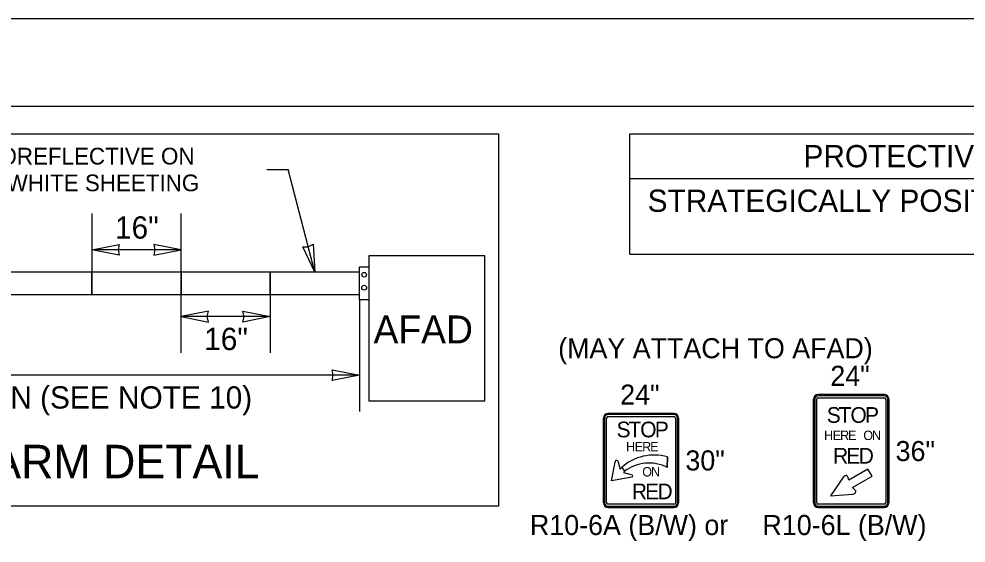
# Model space of a CAD drawing. Extents: x 99999.1 to 100095.7, y 99995 to 100010.7.
# Drawn here: x 100009.243 to 100012.641, y 100008.806 to 100010.687 of the extents above; entities that cross this region are included whole.
import ezdxf

# ---------------------------------------------------------------- set-up
doc = ezdxf.new("R2010")
doc.units = 0
for name, color, linetype in [('SH_GI_PlotLimits', 7, 'Continuous'), ('SH_GI_SheetBorder', 7, 'Continuous'), ('SH_TI_Tables', 7, 'Continuous'), ('TR_SN_ConstructionSigns', 7, 'Continuous'), ('TR_WZ_WorkZoneDetails', 7, 'Continuous')]:
    doc.layers.add(name, color=color, linetype=linetype)

msp = doc.modelspace()

# ---------------------------------------------------------------- linework, layer by layer
at = {"layer": 'SH_GI_PlotLimits'}
msp.add_lwpolyline([(99999.0625, 99999.6875), (100016.0625, 99999.6875), (100016.0625, 100010.6875), (99999.0625, 100010.6875)], close=True, dxfattribs=at)
at = {"layer": 'SH_GI_SheetBorder'}
msp.add_line((100000, 100010.375), (100015.75, 100010.375), dxfattribs=at)
at = {"layer": 'SH_TI_Tables'}
for p, q in [((100011.4347, 100009.843), (100011.4347, 100010.275)), ((100011.4347, 100010.275), (100015.65, 100010.275)), ((100011.4347, 100010.115), (100015.65, 100010.115)), ((100011.4347, 100009.843), (100015.65, 100009.843))]:
    msp.add_line(p, q, dxfattribs=at)
at = {"layer": 'TR_SN_ConstructionSigns'}
for p, q in [((100012.347, 100009.3391), (100012.1108, 100009.3391)), ((100012.1108, 100009.3391), (100012.347, 100009.3391)), ((100012.347, 100009.3391), (100012.1108, 100009.3391)), ((100012.347, 100009.3349), (100012.1108, 100009.3349)), ((100012.0939, 100009.3222), (100012.0939, 100008.951)), ((100012.0939, 100008.951), (100012.0939, 100009.3222)), ((100012.0939, 100009.3222), (100012.0939, 100008.951)), ((100012.0981, 100009.3222), (100012.0981, 100008.951)), ((100012.1052, 100008.951), (100012.1052, 100009.3222)), ((100012.1108, 100009.3279), (100012.347, 100009.3279)), ((100012.3527, 100009.3222), (100012.3527, 100008.951)), ((100012.3597, 100008.951), (100012.3597, 100009.3222)), ((100012.3639, 100008.951), (100012.3639, 100009.3222)), ((100012.3639, 100009.3222), (100012.3639, 100008.951)), ((100012.3639, 100008.951), (100012.3639, 100009.3222)), ((100011.5928, 100009.2716), (100011.3566, 100009.2716)), ((100011.3566, 100009.2716), (100011.5928, 100009.2716)), ((100011.5928, 100009.2716), (100011.3566, 100009.2716)), ((100011.3566, 100009.2716), (100011.5928, 100009.2716)), ((100011.5928, 100009.2674), (100011.3566, 100009.2674)), ((100011.3397, 100009.2547), (100011.3397, 100008.951)), ((100011.3397, 100008.951), (100011.3397, 100009.2547)), ((100011.3397, 100009.2547), (100011.3397, 100008.951)), ((100011.3397, 100008.951), (100011.3397, 100009.2547)), ((100011.3439, 100009.2547), (100011.3439, 100008.951)), ((100011.351, 100008.951), (100011.351, 100009.2547)), ((100011.3566, 100009.2604), (100011.5928, 100009.2604)), ((100011.5985, 100009.2547), (100011.5985, 100008.951)), ((100011.6055, 100008.951), (100011.6055, 100009.2547)), ((100011.6097, 100008.951), (100011.6097, 100009.2547)), ((100011.6097, 100009.2547), (100011.6097, 100008.951)), ((100011.6097, 100008.951), (100011.6097, 100009.2547)), ((100011.6097, 100009.2547), (100011.6097, 100008.951)), ((100011.3692, 100009.0297), (100011.3815, 100009.0967)), ((100011.3912, 100009.1011), (100011.3997, 100009.0719)), ((100011.5692, 100009.1152), (100011.5689, 100009.0774)), ((100011.5689, 100009.0774), (100011.5692, 100009.1152)), ((100011.3997, 100009.0719), (100011.4054, 100009.0776)), ((100011.4054, 100009.0776), (100011.4159, 100009.0642)), ((100011.4054, 100009.0776), (100011.4159, 100009.0642)), ((100011.4159, 100009.0642), (100011.4117, 100009.0599)), ((100012.289, 100009.0719), (100012.22, 100009.0321)), ((100012.3037, 100009.0463), (100012.289, 100009.0719)), ((100011.4423, 100009.0433), (100011.3692, 100009.0297)), ((100011.4117, 100009.0599), (100011.4424, 100009.0517)), ((100012.2015, 100009.0445), (100012.1541, 100008.9764)), ((100012.22, 100009.0321), (100012.2166, 100009.0435)), ((100012.234, 100009.0061), (100012.3037, 100009.0463)), ((100012.2451, 100008.9938), (100012.234, 100009.0061)), ((100012.1541, 100008.9764), (100012.2332, 100008.9819)), ((100011.5928, 100008.9454), (100011.3566, 100008.9454)), ((100011.3566, 100008.9383), (100011.5928, 100008.9383)), ((100011.3566, 100008.9341), (100011.5928, 100008.9341)), ((100011.5928, 100008.9341), (100011.3566, 100008.9341)), ((100011.3566, 100008.9341), (100011.5928, 100008.9341)), ((100011.5928, 100008.9341), (100011.3566, 100008.9341)), ((100012.347, 100008.9454), (100012.1108, 100008.9454)), ((100012.1108, 100008.9383), (100012.347, 100008.9383)), ((100012.1108, 100008.9341), (100012.347, 100008.9341)), ((100012.347, 100008.9341), (100012.1108, 100008.9341)), ((100012.1108, 100008.9341), (100012.347, 100008.9341))]:
    msp.add_line(p, q, dxfattribs=at)
for centre, radius, start, end in [((100012.1108, 100009.3222), 0.0169, 90, 180), ((100012.1108, 100009.3222), 0.0169, 90, 180), ((100012.1108, 100009.3222), 0.0169, 90, 180), ((100012.1108, 100009.3222), 0.0127, 90, 180), ((100012.347, 100009.3222), 0.0169, 0, 90), ((100012.347, 100009.3222), 0.0169, 0, 90), ((100012.347, 100009.3222), 0.0169, 0, 90), ((100012.347, 100009.3222), 0.0127, 0, 90), ((100012.1108, 100009.3222), 0.00562, 90, 180), ((100012.347, 100009.3222), 0.00562, 0, 90), ((100011.3566, 100009.2547), 0.0169, 90, 180), ((100011.3566, 100009.2547), 0.0169, 90, 180), ((100011.3566, 100009.2547), 0.0169, 90, 180), ((100011.3566, 100009.2547), 0.0169, 90, 180), ((100011.3566, 100009.2547), 0.0127, 90, 180), ((100011.5928, 100009.2547), 0.0169, 0, 90), ((100011.5928, 100009.2547), 0.0169, 0, 90), ((100011.5928, 100009.2547), 0.0169, 0, 90), ((100011.5928, 100009.2547), 0.0169, 0, 90), ((100011.5928, 100009.2547), 0.0127, 0, 90), ((100011.3566, 100009.2547), 0.00562, 90, 180), ((100011.5928, 100009.2547), 0.00562, 0, 90), ((100011.5208, 100008.9504), 0.1718, 73.6434, 132.2131), ((100011.5208, 100008.9504), 0.1718, 73.6434, 132.2131), ((100011.5028, 100008.9509), 0.1427, 62.4149, 127.4769), ((100011.5028, 100008.9509), 0.1427, 62.4149, 127.4769), ((100011.3566, 100008.951), 0.0169, 180, 270), ((100011.3566, 100008.951), 0.0169, 180, 270), ((100011.3566, 100008.951), 0.0169, 180, 270), ((100011.3566, 100008.951), 0.0169, 180, 270), ((100011.3566, 100008.951), 0.0127, 180, 270), ((100011.3566, 100008.951), 0.00562, 180, 270), ((100011.5928, 100008.951), 0.0169, 270, 0), ((100011.5928, 100008.951), 0.0169, 270, 0), ((100011.5928, 100008.951), 0.0169, 270, 0), ((100011.5928, 100008.951), 0.0127, 270, 0), ((100011.5928, 100008.951), 0.00562, 270, 0), ((100011.5928, 100008.951), 0.0169, 270, 0), ((100012.1108, 100008.951), 0.0169, 180, 270), ((100012.1108, 100008.951), 0.0169, 180, 270), ((100012.1108, 100008.951), 0.0169, 180, 270), ((100012.1108, 100008.951), 0.0127, 180, 270), ((100012.1108, 100008.951), 0.00562, 180, 270), ((100012.347, 100008.951), 0.0169, 270, 0), ((100012.347, 100008.951), 0.0169, 270, 0), ((100012.347, 100008.951), 0.0169, 270, 0), ((100012.347, 100008.951), 0.0127, 270, 0), ((100012.347, 100008.951), 0.00562, 270, 0)]:
    msp.add_arc(centre, radius, start, end, dxfattribs=at)
for centre, major_axis, ratio, start_param, end_param in [((100011.3873, 100009.0968), (-0.00583, -0.00008), 0.989437, 3.962549, 6.283185), ((100011.4403, 100009.0475), (-0.00414, 0.00215), 0.999053, 2.490568, 4.712389), ((100012.2076, 100009.0406), (0.00841, 0.00485), 0.700347, 5.977036, 8.198856), ((100012.2368, 100008.9893), (-0.00822, -0.00474), 0.700347, 0.771965, 3.092601)]:
    msp.add_ellipse(centre, major_axis=major_axis, ratio=ratio, start_param=start_param, end_param=end_param, dxfattribs=at)
at = {"layer": 'TR_WZ_WorkZoneDetails'}
for p, q in [((100010.1326, 100010.147), (100010.2088, 100010.147)), ((100010.3043, 100009.779), (100010.2088, 100010.147)), ((100009.5043, 100009.989), (100009.5043, 100009.779)), ((100009.8243, 100009.779), (100009.8243, 100009.989)), ((100009.8243, 100009.859), (100009.5043, 100009.859)), ((100009.8243, 100009.489), (100009.8243, 100009.699)), ((100010.1443, 100009.699), (100010.1443, 100009.489)), ((100010.4643, 100009.6797), (100010.4643, 100009.279)), ((100010.1443, 100009.619), (100009.8243, 100009.619)), ((100010.4643, 100009.409), (100008.6643, 100009.409))]:
    msp.add_line(p, q, dxfattribs=at)
for points in [[(100007.6374, 100010.275), (100010.9639, 100010.275), (100010.9639, 100008.939), (100007.6374, 100008.939)], [(100009.5043, 100009.859), (100009.6026, 100009.8783), (100009.5981, 100009.859), (100009.6026, 100009.8397)], [(100009.8243, 100009.859), (100009.7261, 100009.8783), (100009.7306, 100009.859), (100009.7261, 100009.8397)], [(100010.3043, 100009.779), (100010.2611, 100009.8693), (100010.2809, 100009.8697), (100010.2984, 100009.879)], [(100010.4643, 100009.7983), (100010.4977, 100009.7983), (100010.4977, 100009.6797), (100010.4643, 100009.6797)], [(100009.8243, 100009.619), (100009.9226, 100009.5997), (100009.9181, 100009.619), (100009.9226, 100009.6383)], [(100010.1443, 100009.619), (100010.0461, 100009.5997), (100010.0506, 100009.619), (100010.0461, 100009.6383)], [(100010.4643, 100009.409), (100010.3661, 100009.3897), (100010.3706, 100009.409), (100010.3661, 100009.4283)]]:
    msp.add_lwpolyline(points, close=True, dxfattribs=at)
for points in [[(100010.4977, 100009.6797), (100010.4977, 100009.3163), (100010.9139, 100009.3163), (100010.9139, 100009.8374), (100010.4977, 100009.8374), (100010.4977, 100009.7983), (100010.4977, 100009.6797)], [(100010.9139, 100009.8374), (100010.4977, 100009.8374), (100010.4977, 100009.3163), (100010.9139, 100009.3163), (100010.9139, 100009.8374)], [(100010.4643, 100009.779), (100008.6643, 100009.779), (100008.6643, 100009.699), (100010.4643, 100009.699), (100010.4643, 100009.779)], [(100009.1843, 100009.699), (100009.5043, 100009.699), (100009.5043, 100009.779), (100009.1843, 100009.779), (100009.1843, 100009.699)], [(100009.5043, 100009.699), (100009.8243, 100009.699), (100009.8243, 100009.779), (100009.5043, 100009.779), (100009.5043, 100009.699)], [(100009.8243, 100009.699), (100010.1443, 100009.699), (100010.1443, 100009.779), (100009.8243, 100009.779), (100009.8243, 100009.699)], [(100010.1443, 100009.699), (100010.4643, 100009.699), (100010.4643, 100009.779), (100010.1443, 100009.779), (100010.1443, 100009.699)]]:
    msp.add_lwpolyline(points, dxfattribs=at)
for centre, radius in [((100010.4813, 100009.7693), 0.00828), ((100010.4813, 100009.7229), 0.00855)]:
    msp.add_circle(centre, radius, dxfattribs=at)

# ---------------------------------------------------------------- texts
at = {"layer": 'SH_TI_Tables'}
for s, p in [('PROTECTIVE VEHICLE ROLL AHEAD DISTANCE = R', (100012.0577, 100010.155)), ('STRATEGICALLY POSITION WORK VEHICLE TO PROTECT WORK CREW.', (100011.4984, 100009.995))]:
    msp.add_text(s, height=0.08, rotation=360, dxfattribs=at).set_placement(p)
at = {"layer": 'TR_SN_ConstructionSigns'}
for s, p in [('(MAY ATTACH TO AFAD)', (100011.1775, 100009.4696)), ('24"', (100012.1539, 100009.3706)), ('24"', (100011.3999, 100009.3031)), ('36"', (100012.3882, 100009.1006)), ('30"', (100011.634, 100009.0669)), ('R10-6A (B/W) or', (100011.0761, 100008.8351)), ('R10-6L (B/W)', (100011.9104, 100008.8351))]:
    msp.add_text(s, height=0.072, rotation=360, dxfattribs=at).set_placement(p)
for s, height, p in [('S', 0.0562, (100012.1412, 100009.2379)), ('T', 0.0562, (100012.1839, 100009.2379)), ('O', 0.0562, (100012.2261, 100009.2379)), ('P', 0.0562, (100012.2784, 100009.2379)), ('S', 0.0562, (100011.387, 100009.1858)), ('T', 0.0562, (100011.4297, 100009.1858)), ('O', 0.0562, (100011.4719, 100009.1858)), ('P', 0.0562, (100011.5242, 100009.1858)), ('H', 0.0338, (100012.1312, 100009.176)), ('E', 0.0338, (100012.1623, 100009.176)), ('R', 0.0338, (100012.1889, 100009.176)), ('E', 0.0338, (100012.2176, 100009.176)), ('O', 0.0338, (100012.2723, 100009.176)), ('N', 0.0338, (100012.3037, 100009.176)), ('H', 0.0338, (100011.421, 100009.1352)), ('E', 0.0338, (100011.4521, 100009.1352)), ('R', 0.0338, (100011.4788, 100009.1352)), ('E', 0.0338, (100011.5074, 100009.1352)), ('R', 0.0562, (100012.1637, 100009.0916)), ('E', 0.0562, (100012.2115, 100009.0916)), ('D', 0.0562, (100012.2559, 100009.0916)), ('O', 0.0338, (100011.4791, 100009.0452)), ('N', 0.0338, (100011.5105, 100009.0452)), ('R', 0.0562, (100011.4417, 100008.9636)), ('E', 0.0562, (100011.4895, 100008.9636)), ('D', 0.0562, (100011.5339, 100008.9636))]:
    msp.add_text(s, height=height, dxfattribs=at).set_placement(p)
at = {"layer": 'TR_WZ_WorkZoneDetails'}
for s, height, p in [('GATE ARM SHALL BE FULLY RETROREFLECTIVE ON', 0.06, (100007.8352, 100010.165)), ('BOTH SIDES WITH ALTERNATING RED/WHITE SHEETING', 0.06, (100007.6874, 100010.069)), ('16"', 0.08, (100009.5873, 100009.899)), ('AFAD', 0.1, (100010.5149, 100009.5231)), ('16"', 0.08, (100009.9073, 100009.499)), ('78" MIN (SEE NOTE 10)', 0.08, (100008.9061, 100009.289))]:
    msp.add_text(s, height=height, dxfattribs=at).set_placement(p)
msp.add_text('AFAD GATE ARM DETAIL', height=0.12, rotation=360, dxfattribs=at).set_placement((100008.1893, 100009.039))

doc.saveas('drawing.dxf')
